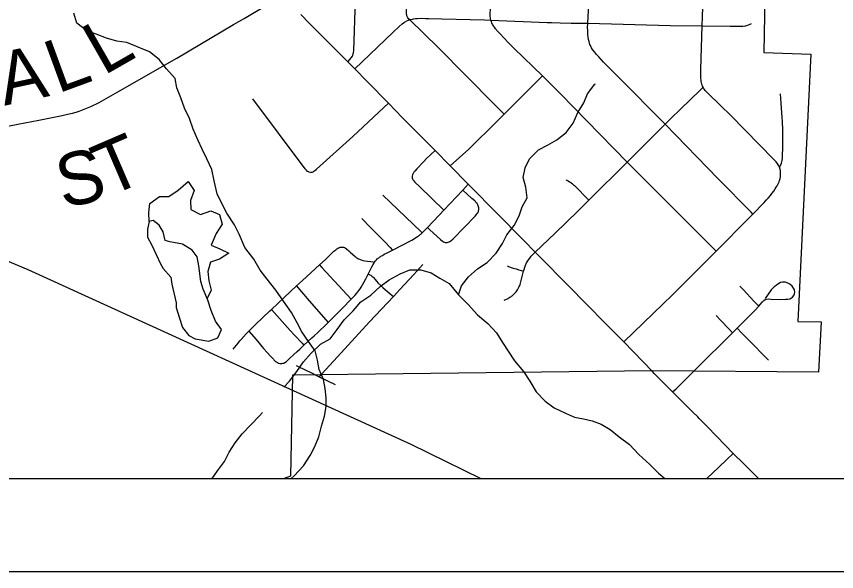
# Model space of a CAD drawing. Extents: x 0 to 34, y 0 to 22.
# Drawn here: x 24.841 to 25.722, y 13.024 to 13.62 of the extents above; entities that cross this region are included whole.
import ezdxf

# ---------------------------------------------------------------- set-up
doc = ezdxf.new("R2010")
doc.units = 0
for name, color, linetype in [('GM_X_City_Street', 7, 'Continuous'), ('GM_X_Corporation', 7, 'Continuous'), ('GM_X_County_Road', 7, 'Continuous'), ('GM_X_County_Road_Text', 7, 'Continuous'), ('GM_X_Minor_Lake', 7, 'Continuous'), ('GM_X_Minor_River', 7, 'Continuous'), ('GM_X_Rail_Line', 7, 'Continuous'), ('GM_X_Township_Road', 7, 'Continuous'), ('SH_Data', 7, 'Continuous')]:
    doc.layers.add(name, color=color, linetype=linetype)

msp = doc.modelspace()

# ---------------------------------------------------------------- linework, layer by layer
at = {"layer": 'GM_X_City_Street'}
msp.add_lwpolyline([(25.58226, 13.12386), (25.5951, 13.13623), (25.60364, 13.1444), (25.61043, 13.15089)], dxfattribs=at)
at = {"layer": 'GM_X_Corporation'}
for points in [[(23.44381, 15.60337), (23.44381, 13.12386), (28.80084, 13.12386)], [(25.9489, 14.19414), (25.62479, 14.19306), (25.62469, 14.05158), (25.62469, 14.04756), (25.62491, 13.98235), (25.64242, 13.98248), (25.65046, 13.98251), (25.64348, 13.58164), (25.69378, 13.57975), (25.67991, 13.29262), (25.70516, 13.29209), (25.70202, 13.23813), (25.52351, 13.2394), (25.13706, 13.23479), (25.13492, 13.12631), (25.12831, 13.12386), (27.32647, 13.12386)]]:
    msp.add_lwpolyline(points, dxfattribs=at)
at = {"layer": 'GM_X_County_Road'}
for p, q in [((25.20408, 13.56391), (25.1964, 13.57164)), ((25.30642, 13.45982), (25.29025, 13.47626)), ((25.32596, 13.43998), (25.30642, 13.45982)), ((25.52371, 13.23884), (25.49291, 13.27055))]:
    msp.add_line(p, q, dxfattribs=at)
for points in [[(25.08509, 13.61825), (25.10751, 13.63146), (25.11333, 13.6352), (25.11821, 13.63867), (25.12158, 13.64138), (25.12462, 13.6442)], [(25.1964, 13.57164), (25.1652, 13.60306), (25.15546, 13.61281), (25.146, 13.62244)], [(24.94952, 13.53936), (25.01296, 13.57557), (25.07389, 13.61164), (25.08509, 13.61825)], [(25.24013, 13.52712), (25.21718, 13.55059), (25.20408, 13.56391)], [(24.75834, 13.4807), (24.75938, 13.48128), (24.76221, 13.48292), (24.76808, 13.48587), (24.77327, 13.48828), (24.77988, 13.49079), (24.78901, 13.49376), (24.7993, 13.49623), (24.80695, 13.49781), (24.81646, 13.49958), (24.84212, 13.50441), (24.86468, 13.50889), (24.88981, 13.51403), (24.89526, 13.51524), (24.9007, 13.51653), (24.90459, 13.51758), (24.90804, 13.51867), (24.91139, 13.51984), (24.91511, 13.52127), (24.92053, 13.52354), (24.92953, 13.52795), (24.94952, 13.53936)], [(25.29025, 13.47626), (25.28421, 13.4823), (25.25543, 13.51149), (25.24013, 13.52712)], [(25.39796, 13.36696), (25.38583, 13.37918), (25.35579, 13.40976), (25.32872, 13.43717), (25.32596, 13.43998)], [(25.49291, 13.27055), (25.46881, 13.2952), (25.45746, 13.30671), (25.42901, 13.33537), (25.40685, 13.35801), (25.39796, 13.36696)], [(25.54549, 13.21713), (25.5257, 13.2368), (25.52371, 13.23884)], [(25.61043, 13.15089), (25.59305, 13.16884), (25.58237, 13.18014), (25.57401, 13.18849), (25.5724, 13.19004), (25.56682, 13.19558), (25.54549, 13.21713)], [(25.63771, 13.12386), (25.63195, 13.12957), (25.62178, 13.13961), (25.61043, 13.15089)]]:
    msp.add_lwpolyline(points, dxfattribs=at)
at = {"layer": 'GM_X_Minor_Lake'}
msp.add_line((25.0076, 13.33259), (25.0123, 13.31252), dxfattribs=at)
msp.add_lwpolyline([(25.0123, 13.31252), (25.01233, 13.30759), (25.01544, 13.29738), (25.01893, 13.28603), (25.02582, 13.27736), (25.03265, 13.274), (25.04743, 13.27146), (25.05687, 13.27494), (25.06096, 13.28408), (25.05446, 13.29275), (25.04983, 13.30447), (25.04634, 13.31544), (25.04132, 13.32716), (25.03861, 13.33548), (25.03658, 13.35253), (25.03462, 13.362), (25.02926, 13.36916), (25.019, 13.37553), (25.00914, 13.37735), (25.00535, 13.37808), (25.00042, 13.37956), (24.99807, 13.38902), (24.99386, 13.39619), (24.98738, 13.40108), (24.98323, 13.39991), (24.9814, 13.39193), (24.98147, 13.38321), (24.98608, 13.37452), (24.99532, 13.35449), (24.99838, 13.34958), (25.0064, 13.34016), (25.0076, 13.33259)], dxfattribs=at)
at = {"layer": 'GM_X_Minor_River'}
for points in [[(24.94841, 13.5938), (24.93741, 13.59713), (24.9264, 13.60122), (24.91615, 13.60493), (24.90549, 13.61319), (24.90238, 13.62379)], [(25.13568, 13.12386), (25.13901, 13.1269), (25.14877, 13.1376), (25.15625, 13.14865), (25.1611, 13.15817), (25.16556, 13.16883), (25.16812, 13.18022), (25.17144, 13.19087), (25.17325, 13.20112), (25.17318, 13.2106), (25.17235, 13.22046), (25.17038, 13.2303), (25.16575, 13.24088), (25.16416, 13.25111), (25.16144, 13.26095), (25.15417, 13.27113), (25.14728, 13.28132), (25.14228, 13.29114), (25.13614, 13.3021), (25.12734, 13.31454), (25.1193, 13.32624), (25.10975, 13.33792), (25.10248, 13.34773), (25.09557, 13.35943), (25.08601, 13.37225), (25.07985, 13.38624), (25.07485, 13.39644), (25.06643, 13.40889), (25.06143, 13.41871), (25.05604, 13.42966), (25.05291, 13.44367), (25.05054, 13.45579), (25.04515, 13.46751), (25.04015, 13.47771), (25.03553, 13.48791), (25.03052, 13.49925), (25.02665, 13.51059), (25.02126, 13.52193), (25.01701, 13.5329), (25.01277, 13.54348), (25.01118, 13.55371), (25.00163, 13.56387), (24.99398, 13.57405), (24.9837, 13.58232), (24.97383, 13.58641), (24.95902, 13.59237), (24.94841, 13.5938)], [(25.31539, 13.32129), (25.31872, 13.3308), (25.32621, 13.34072), (25.33599, 13.34913), (25.34615, 13.35604), (25.35592, 13.36597), (25.36265, 13.37626), (25.3675, 13.38578), (25.37537, 13.3957), (25.38059, 13.40598), (25.38392, 13.41587), (25.38914, 13.42539), (25.38792, 13.43676), (25.38481, 13.44735), (25.387, 13.45761), (25.39184, 13.4675), (25.40123, 13.47706), (25.41103, 13.48206), (25.4212, 13.48783), (25.43098, 13.49549), (25.43847, 13.50578), (25.44368, 13.5172), (25.45004, 13.52749), (25.45413, 13.537), (25.46199, 13.54768), (25.46275, 13.54806)], [(24.98323, 13.39991), (24.98277, 13.40976), (24.98384, 13.41925), (24.99437, 13.42692), (25.00422, 13.42699), (25.01438, 13.43352), (25.02491, 13.44308), (25.03142, 13.43327), (25.02772, 13.42262), (25.02779, 13.41276), (25.03843, 13.40754), (25.04937, 13.41141), (25.05887, 13.40769), (25.0616, 13.39709), (25.05524, 13.38719), (25.04966, 13.37463), (25.05915, 13.37053), (25.06865, 13.36605), (25.05886, 13.35953), (25.04904, 13.35642), (25.0461, 13.34616), (25.04731, 13.33631), (25.04966, 13.32608), (25.04553, 13.31732)], [(25.12789, 13.22207), (25.13406, 13.22851), (25.14193, 13.23881), (25.14904, 13.2491), (25.15729, 13.25864), (25.16706, 13.2682), (25.17761, 13.27397), (25.1851, 13.28389), (25.19259, 13.29419), (25.20236, 13.30412), (25.21061, 13.31366), (25.22115, 13.32095), (25.2313, 13.33013), (25.24108, 13.33741), (25.25276, 13.34395), (25.26333, 13.3482), (25.27506, 13.34791), (25.28606, 13.34496), (25.29557, 13.33897), (25.30546, 13.33335), (25.31539, 13.32129), (25.32569, 13.31075), (25.33599, 13.29983), (25.34704, 13.29044), (25.3562, 13.28027), (25.36272, 13.27008), (25.37574, 13.25045), (25.38529, 13.23877), (25.39218, 13.22858), (25.39871, 13.21688), (25.40862, 13.20709), (25.41814, 13.19996), (25.4303, 13.19398), (25.44017, 13.18989), (25.44964, 13.18806), (25.45912, 13.18586), (25.46861, 13.18214), (25.4785, 13.17653), (25.48802, 13.16864), (25.49906, 13.16038), (25.50898, 13.14983), (25.5208, 13.13892), (25.53033, 13.12952), (25.53707, 13.12386)], [(25.05098, 13.12386), (25.05646, 13.13196), (25.06395, 13.14226), (25.06917, 13.15216), (25.07553, 13.16207), (25.08303, 13.17199), (25.1018, 13.19109), (25.1048, 13.19491)]]:
    msp.add_lwpolyline(points, dxfattribs=at)
at = {"layer": 'GM_X_Rail_Line'}
msp.add_lwpolyline([(23.44381, 13.3271), (23.521, 13.31215), (23.6525, 13.29246), (23.70823, 13.28473), (23.75761, 13.27949), (23.8057, 13.2772), (23.84696, 13.27802), (23.88857, 13.28157), (23.9419, 13.28973), (23.98688, 13.29785), (24.08722, 13.30831), (24.24377, 13.32768), (24.42723, 13.35829), (24.62573, 13.38259), (24.68089, 13.38534), (24.72463, 13.38394), (24.76114, 13.37909), (24.78933, 13.3718), (24.8141, 13.36445), (24.8529, 13.34856), (25.26415, 13.16081), (25.33926, 13.12386)], dxfattribs=at)
at = {"layer": 'GM_X_Township_Road'}
msp.add_line((25.45556, 13.42303), (25.49659, 13.4638), dxfattribs=at)
for points in [[(25.1964, 13.57164), (25.20041, 13.57634), (25.20107, 13.57723), (25.20142, 13.57776), (25.20193, 13.57878), (25.20237, 13.58003), (25.20261, 13.58111), (25.20275, 13.58208), (25.20284, 13.58323), (25.20486, 13.63763), (25.20642, 13.66499), (25.20658, 13.66731), (25.20666, 13.66834), (25.2068, 13.66982), (25.20692, 13.67084), (25.20706, 13.67176), (25.20734, 13.67287), (25.20766, 13.67358), (25.20801, 13.67429), (25.20859, 13.67507), (25.20928, 13.67584)], [(25.26299, 13.6168), (25.26188, 13.61791), (25.26101, 13.6189), (25.26055, 13.6196), (25.26026, 13.62025), (25.26004, 13.62091), (25.25982, 13.62188), (25.2597, 13.62288), (25.2597, 13.62593), (25.25983, 13.63018), (25.26, 13.63519), (25.26163, 13.67713)], [(25.35018, 13.61626), (25.34985, 13.61789), (25.34974, 13.61881), (25.34962, 13.62013), (25.34954, 13.62152), (25.34953, 13.62284), (25.34956, 13.62429), (25.34965, 13.62711), (25.34992, 13.63238), (25.35051, 13.64717), (25.35159, 13.66812), (25.35187, 13.67434)], [(25.45429, 13.61302), (25.45495, 13.62671), (25.45629, 13.66218), (25.45661, 13.67116)], [(25.57721, 13.61019), (25.57751, 13.6203), (25.57948, 13.66803)], [(25.20408, 13.56391), (25.24473, 13.60324), (25.25159, 13.60967), (25.25495, 13.61248), (25.25759, 13.61429), (25.2599, 13.61555), (25.26168, 13.61635), (25.26299, 13.6168)], [(25.26299, 13.6168), (25.26424, 13.61717), (25.26599, 13.61754), (25.26726, 13.61776), (25.26924, 13.618), (25.27087, 13.61814), (25.27605, 13.61829), (25.28017, 13.61827), (25.2834, 13.61818), (25.29756, 13.61763), (25.34336, 13.61656), (25.35018, 13.61626)], [(25.36451, 13.5153), (25.3599, 13.51992), (25.35374, 13.52606), (25.29353, 13.58695), (25.26299, 13.6168)], [(25.35018, 13.61626), (25.41061, 13.61397), (25.41548, 13.61379), (25.42479, 13.61346), (25.43655, 13.6132), (25.45429, 13.61302)], [(25.40559, 13.5565), (25.37531, 13.58602), (25.36895, 13.59247), (25.36408, 13.59747), (25.36026, 13.60147), (25.35905, 13.60274), (25.35799, 13.60388), (25.35679, 13.60524), (25.35614, 13.60599), (25.3553, 13.60709), (25.35396, 13.60896), (25.35298, 13.61038), (25.35243, 13.61132), (25.35196, 13.61212), (25.35132, 13.61327), (25.35076, 13.61451), (25.3504, 13.61549), (25.35018, 13.61626)], [(25.53738, 13.50455), (25.52931, 13.5128), (25.51971, 13.52249), (25.50481, 13.53742), (25.49476, 13.5476), (25.47124, 13.57136), (25.46621, 13.57675), (25.46365, 13.5796), (25.46151, 13.58218), (25.45948, 13.58494), (25.45844, 13.5866), (25.45718, 13.58899), (25.45667, 13.59017), (25.4561, 13.59175), (25.45567, 13.59324), (25.45513, 13.59551), (25.45466, 13.5981), (25.45441, 13.60079), (25.45427, 13.60302), (25.45421, 13.60557), (25.45419, 13.60821), (25.45429, 13.61302)], [(25.45429, 13.61302), (25.5427, 13.61055), (25.57721, 13.61019)], [(25.57721, 13.61019), (25.60724, 13.60987), (25.61666, 13.60972), (25.61984, 13.6098), (25.6209, 13.60988), (25.62292, 13.61012), (25.62402, 13.61031), (25.62584, 13.6108), (25.62698, 13.6112), (25.6289, 13.612), (25.63015, 13.61263)], [(25.5782, 13.54419), (25.57765, 13.54552), (25.57721, 13.54667), (25.57692, 13.54763), (25.57657, 13.54885), (25.57626, 13.55044), (25.57604, 13.55198), (25.57585, 13.55397), (25.57572, 13.55612), (25.57583, 13.56314), (25.57721, 13.61019)], [(25.36451, 13.5153), (25.36844, 13.51921), (25.39535, 13.54614), (25.40559, 13.5565)], [(25.49659, 13.4638), (25.4531, 13.50841), (25.4255, 13.53664), (25.41454, 13.54771), (25.40989, 13.55233), (25.40559, 13.5565)], [(25.53738, 13.50455), (25.54316, 13.51032), (25.55432, 13.52115), (25.57451, 13.54063), (25.5782, 13.54419)], [(25.66036, 13.45836), (25.65964, 13.45995), (25.6586, 13.46171), (25.65677, 13.46398), (25.65425, 13.46671), (25.60753, 13.51424), (25.59733, 13.52431), (25.58284, 13.53819), (25.58143, 13.53968), (25.58035, 13.54086), (25.57952, 13.54197), (25.57879, 13.54315), (25.5782, 13.54419)], [(25.66036, 13.45836), (25.66183, 13.46105), (25.66252, 13.46253), (25.66294, 13.464), (25.6632, 13.46569), (25.66336, 13.4679), (25.6639, 13.48196), (25.66396, 13.48491), (25.664, 13.48935), (25.66398, 13.49325), (25.66393, 13.49517), (25.66382, 13.49852), (25.66372, 13.50106), (25.66354, 13.50481), (25.66339, 13.50744), (25.66308, 13.51184), (25.66202, 13.52722), (25.66134, 13.53734)], [(25.15652, 13.45275), (25.15519, 13.45299), (25.15415, 13.45335), (25.15332, 13.45388), (25.15209, 13.45499), (25.15074, 13.45655), (25.09468, 13.53165)], [(25.15652, 13.45275), (25.15765, 13.45286), (25.15852, 13.45307), (25.15924, 13.45337), (25.16013, 13.45392), (25.16091, 13.45452), (25.16275, 13.45609), (25.20204, 13.49139), (25.23524, 13.52232), (25.24013, 13.52712)], [(25.30642, 13.45982), (25.32668, 13.47785), (25.35714, 13.50796), (25.36451, 13.5153)], [(25.49659, 13.4638), (25.50621, 13.47339), (25.52378, 13.49097), (25.53738, 13.50455)], [(25.63168, 13.40791), (25.62976, 13.40988), (25.59452, 13.446), (25.53738, 13.50455)], [(25.29025, 13.47626), (25.28121, 13.46769), (25.27811, 13.46458), (25.27058, 13.45661), (25.26843, 13.45407), (25.26763, 13.45296), (25.26667, 13.45158), (25.26627, 13.45088), (25.26596, 13.45022), (25.26567, 13.44886), (25.26564, 13.44806), (25.2658, 13.44697), (25.26613, 13.4459), (25.26649, 13.44508), (25.26683, 13.44453), (25.26733, 13.44383), (25.26864, 13.4424), (25.27344, 13.43744), (25.29986, 13.41229)], [(25.59224, 13.36826), (25.58968, 13.37081), (25.49659, 13.4638)], [(25.63168, 13.40791), (25.64379, 13.4204), (25.64635, 13.42319), (25.64801, 13.42508), (25.65046, 13.42804), (25.6522, 13.43025), (25.65405, 13.43272), (25.65571, 13.43507), (25.65682, 13.43674), (25.65768, 13.43823), (25.65849, 13.43972), (25.65927, 13.44125), (25.65994, 13.44278), (25.66043, 13.4442), (25.66093, 13.446), (25.66132, 13.4482), (25.66147, 13.45005), (25.66146, 13.45252), (25.66127, 13.45438), (25.66101, 13.45606), (25.66066, 13.45737), (25.66036, 13.45836)], [(25.4307, 13.44493), (25.43199, 13.44431), (25.43269, 13.44397), (25.43337, 13.44361), (25.43475, 13.4428), (25.43532, 13.44242), (25.436, 13.44195), (25.43663, 13.44145), (25.43777, 13.44048), (25.43898, 13.43941), (25.43989, 13.43855), (25.45556, 13.42303)], [(25.09015, 13.28204), (25.09796, 13.27312), (25.10115, 13.26943), (25.10421, 13.26582), (25.10604, 13.26373), (25.11001, 13.25941), (25.11357, 13.25535), (25.11659, 13.25202), (25.1172, 13.25139), (25.11817, 13.25046), (25.11897, 13.24976), (25.11983, 13.24908), (25.12086, 13.24842), (25.12218, 13.24776), (25.12358, 13.24748), (25.12481, 13.24739), (25.12574, 13.24746), (25.12684, 13.24767), (25.12776, 13.24796), (25.12862, 13.24833), (25.12981, 13.24913), (25.13059, 13.24976), (25.13146, 13.25048), (25.13408, 13.25286), (25.13859, 13.25704), (25.14213, 13.26046), (25.14485, 13.26289), (25.14931, 13.267), (25.15806, 13.27491), (25.16033, 13.277), (25.16443, 13.28078), (25.17404, 13.29), (25.17548, 13.29143), (25.17841, 13.29433), (25.18381, 13.29981), (25.19078, 13.30685), (25.20026, 13.31673), (25.20399, 13.32059), (25.20619, 13.32308), (25.20843, 13.32582), (25.20978, 13.3277), (25.21102, 13.32958), (25.21245, 13.33193), (25.21602, 13.33838), (25.21853, 13.34356), (25.22236, 13.35146), (25.22363, 13.35382), (25.22434, 13.35498), (25.22494, 13.35587), (25.22538, 13.35648), (25.2261, 13.35745), (25.22653, 13.35797), (25.22736, 13.35889), (25.2282, 13.35973), (25.22869, 13.36017), (25.2292, 13.3606), (25.2297, 13.36099), (25.23046, 13.36152), (25.2314, 13.36214), (25.23212, 13.36262), (25.23365, 13.36357), (25.23572, 13.36478), (25.2382, 13.36608), (25.2444, 13.36918), (25.26531, 13.38003), (25.27039, 13.3831), (25.27232, 13.38443), (25.27305, 13.38497), (25.27425, 13.38595), (25.27489, 13.38649), (25.27589, 13.38736), (25.27648, 13.38792), (25.27864, 13.38994), (25.28215, 13.39353), (25.29463, 13.40675), (25.29986, 13.41229), (25.32009, 13.43375), (25.32596, 13.43998)], [(25.23403, 13.42839), (25.27507, 13.38927), (25.27648, 13.38792)], [(25.28215, 13.39353), (25.28483, 13.39106), (25.29604, 13.38068), (25.29832, 13.37874), (25.29918, 13.37822), (25.30029, 13.37774), (25.3011, 13.37755), (25.3023, 13.37744), (25.3033, 13.37752), (25.30427, 13.37775), (25.30533, 13.37814), (25.30627, 13.37863), (25.30716, 13.37928), (25.30958, 13.38153), (25.33317, 13.40589), (25.33489, 13.4077), (25.33574, 13.4088), (25.3364, 13.40983), (25.33687, 13.41093), (25.33706, 13.41167), (25.33719, 13.41239), (25.33725, 13.41319), (25.33715, 13.4148), (25.33701, 13.41559), (25.3367, 13.41667), (25.33618, 13.41784), (25.33579, 13.41851), (25.33534, 13.4192), (25.33454, 13.42019), (25.33353, 13.42135), (25.33282, 13.42211), (25.3298, 13.42489), (25.32009, 13.43375)], [(25.39796, 13.36696), (25.41913, 13.38743), (25.44369, 13.41124), (25.45556, 13.42303)], [(25.21154, 13.40311), (25.22093, 13.39371), (25.23096, 13.38366), (25.23631, 13.3781), (25.24203, 13.37194), (25.2444, 13.36918)], [(25.59224, 13.36826), (25.62773, 13.40384), (25.63168, 13.40791)], [(25.07327, 13.26271), (25.07865, 13.26932), (25.08067, 13.27175), (25.08203, 13.27332), (25.08738, 13.27918), (25.08915, 13.28104), (25.09015, 13.28204), (25.09752, 13.28947), (25.11281, 13.30395), (25.11449, 13.30556), (25.12813, 13.3185), (25.14137, 13.33072), (25.14777, 13.33662), (25.16615, 13.35338), (25.17209, 13.35879), (25.1817, 13.3681), (25.18266, 13.36899), (25.18353, 13.36971), (25.18435, 13.37035), (25.18493, 13.37074), (25.18565, 13.37117), (25.1863, 13.37152), (25.18726, 13.37196), (25.18849, 13.37235), (25.18924, 13.37251), (25.18995, 13.37258), (25.19123, 13.37252), (25.192, 13.37234), (25.19298, 13.37199), (25.19381, 13.37156), (25.19496, 13.37072), (25.19749, 13.36851), (25.19891, 13.36722), (25.20191, 13.36442), (25.20437, 13.36229), (25.20558, 13.36136), (25.2061, 13.36101), (25.20724, 13.36034), (25.20796, 13.35995), (25.20902, 13.35945), (25.20974, 13.35915), (25.21099, 13.3587), (25.21254, 13.35825), (25.21478, 13.35777), (25.21781, 13.3573), (25.22112, 13.35692), (25.22365, 13.35665), (25.22538, 13.35648)], [(25.38537, 13.34679), (25.38589, 13.34857), (25.38665, 13.35095), (25.38745, 13.35308), (25.38808, 13.35454), (25.38855, 13.35554), (25.3899, 13.35789), (25.39084, 13.35928), (25.39274, 13.36178), (25.39356, 13.36275), (25.39411, 13.36337), (25.39476, 13.36404), (25.39567, 13.3649), (25.39631, 13.36547), (25.39796, 13.36696)], [(25.49291, 13.27055), (25.52473, 13.30116), (25.54524, 13.32115), (25.59224, 13.36826)], [(25.16581, 13.23317), (25.16864, 13.23626), (25.18547, 13.25459), (25.22001, 13.29207), (25.24557, 13.31955), (25.25244, 13.32694), (25.26741, 13.34319), (25.27712, 13.35381)], [(25.16615, 13.35338), (25.16868, 13.35062), (25.20026, 13.31673)], [(25.36812, 13.35237), (25.36919, 13.35183), (25.37026, 13.35136), (25.37193, 13.3507), (25.37314, 13.35028), (25.37408, 13.34998), (25.37552, 13.34953), (25.37729, 13.34902), (25.38018, 13.34821), (25.38537, 13.34679)], [(25.21853, 13.34356), (25.21951, 13.34309), (25.22017, 13.34276), (25.22123, 13.34219), (25.22232, 13.34141), (25.22338, 13.34046), (25.22399, 13.33984), (25.22596, 13.33756), (25.22731, 13.33607), (25.2293, 13.33393), (25.23224, 13.33099), (25.23427, 13.32909), (25.24216, 13.32236), (25.24557, 13.31955)], [(25.36461, 13.31565), (25.36711, 13.31665), (25.36802, 13.31707), (25.36874, 13.31744), (25.36964, 13.31793), (25.37068, 13.31855), (25.37158, 13.31916), (25.37225, 13.31962), (25.37305, 13.32024), (25.37352, 13.32065), (25.37414, 13.3212), (25.37494, 13.32193), (25.37555, 13.32255), (25.37638, 13.32345), (25.37723, 13.32444), (25.37808, 13.32558), (25.37885, 13.32672), (25.37927, 13.32738), (25.38, 13.32866), (25.38037, 13.32937), (25.38077, 13.33024), (25.38123, 13.33132), (25.38161, 13.33244), (25.38205, 13.3339), (25.38537, 13.34679)], [(25.14137, 13.33072), (25.14468, 13.32685), (25.14896, 13.32185), (25.15496, 13.31483), (25.1728, 13.29449), (25.17548, 13.29143)], [(25.54549, 13.21713), (25.5491, 13.22033), (25.57037, 13.24133), (25.60969, 13.28051), (25.61214, 13.28294), (25.61468, 13.28545), (25.63383, 13.30434), (25.63802, 13.30899), (25.63957, 13.31072), (25.642, 13.31355), (25.64351, 13.31516), (25.64482, 13.31617), (25.64613, 13.31667), (25.64845, 13.31677), (25.65114, 13.31655), (25.66052, 13.31626), (25.66679, 13.31646), (25.66911, 13.31666), (25.67124, 13.31706), (25.6732, 13.31783), (25.67435, 13.3187), (25.67567, 13.32037), (25.67645, 13.32235), (25.67666, 13.32446), (25.67628, 13.32653), (25.67539, 13.32841), (25.67375, 13.33053), (25.67118, 13.33261), (25.66841, 13.33419), (25.6667, 13.3347), (25.66485, 13.33497), (25.66347, 13.33493), (25.66146, 13.33432), (25.65859, 13.33275), (25.65652, 13.33128), (25.65455, 13.32966), (25.65142, 13.32647), (25.64795, 13.32181), (25.64502, 13.31727)], [(25.63802, 13.30899), (25.63285, 13.31453), (25.62169, 13.32647), (25.61776, 13.33055)], [(25.11449, 13.30556), (25.11746, 13.30222), (25.13472, 13.28289), (25.13932, 13.27787), (25.14736, 13.26912), (25.14931, 13.267)], [(25.60969, 13.28051), (25.60619, 13.28419), (25.59691, 13.29397), (25.59227, 13.29886)], [(25.64843, 13.25109), (25.645, 13.25473), (25.62955, 13.27019), (25.61957, 13.28043), (25.61468, 13.28545)], [(25.14123, 13.24546), (25.15218, 13.23986), (25.15593, 13.23797), (25.16581, 13.23317), (25.18293, 13.22483)]]:
    msp.add_lwpolyline(points, dxfattribs=at)
at = {"layer": 'SH_Data'}
for p, q in [((23.44381, 13.12386), (30.24381, 13.12386)), ((23.34381, 13.02386), (30.34381, 13.02386))]:
    msp.add_line(p, q, dxfattribs=at)

# ---------------------------------------------------------------- texts
at = {"layer": 'GM_X_County_Road_Text'}
for s, rotation, p in [('L', 29.8001, (24.93422, 13.55628)), ('L', 20.13301, (24.88483, 13.53723)), ('A', 12.10366, (24.82759, 13.52433)), ('T', 23.31254, (24.9388, 13.42583)), ('S', 12.67517, (24.89046, 13.41387))]:
    msp.add_text(s, height=0.05682, rotation=rotation, dxfattribs=at).set_placement(p)

doc.saveas('drawing.dxf')
